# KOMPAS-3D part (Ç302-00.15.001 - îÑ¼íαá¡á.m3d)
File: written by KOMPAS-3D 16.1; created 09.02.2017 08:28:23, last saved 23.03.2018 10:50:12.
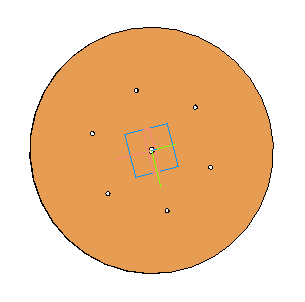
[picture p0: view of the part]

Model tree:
1. Эскиз:7
2. Операция выдавливания:12
     Расстояние 1 = 4; Расстояние 2 = 24.8832
3. Эскиз:8
4. Вырезать элемент выдавливания:1
     Расстояние 1 = 0.1
5. Зеркальный массив:1
6. Экземпляр ( 1 )
7. Экземпляр ( 2 )  (with: Вырезать элемент выдавливания:1)
8. Эскиз:9
9. Вырезать элемент выдавливания:2
     Расстояние 1 = 10
10. Массив по концентрической сетке:1  (with: Вырезать элемент выдавливания:2, Эскиз:9)  (labels: А302-00.15.001)  (6 pattern instances)
     Геометрический массив = 5; Шаг 2 = 360

Expressions: 250+28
